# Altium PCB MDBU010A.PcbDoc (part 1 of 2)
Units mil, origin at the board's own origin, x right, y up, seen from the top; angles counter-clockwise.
Board outline 3300 x 2500 mil, 2 copper layers (Top Layer, Bottom Layer), stack 64.8 mil thick; 105 components, 70 nets, 307 pads, 460 vias.
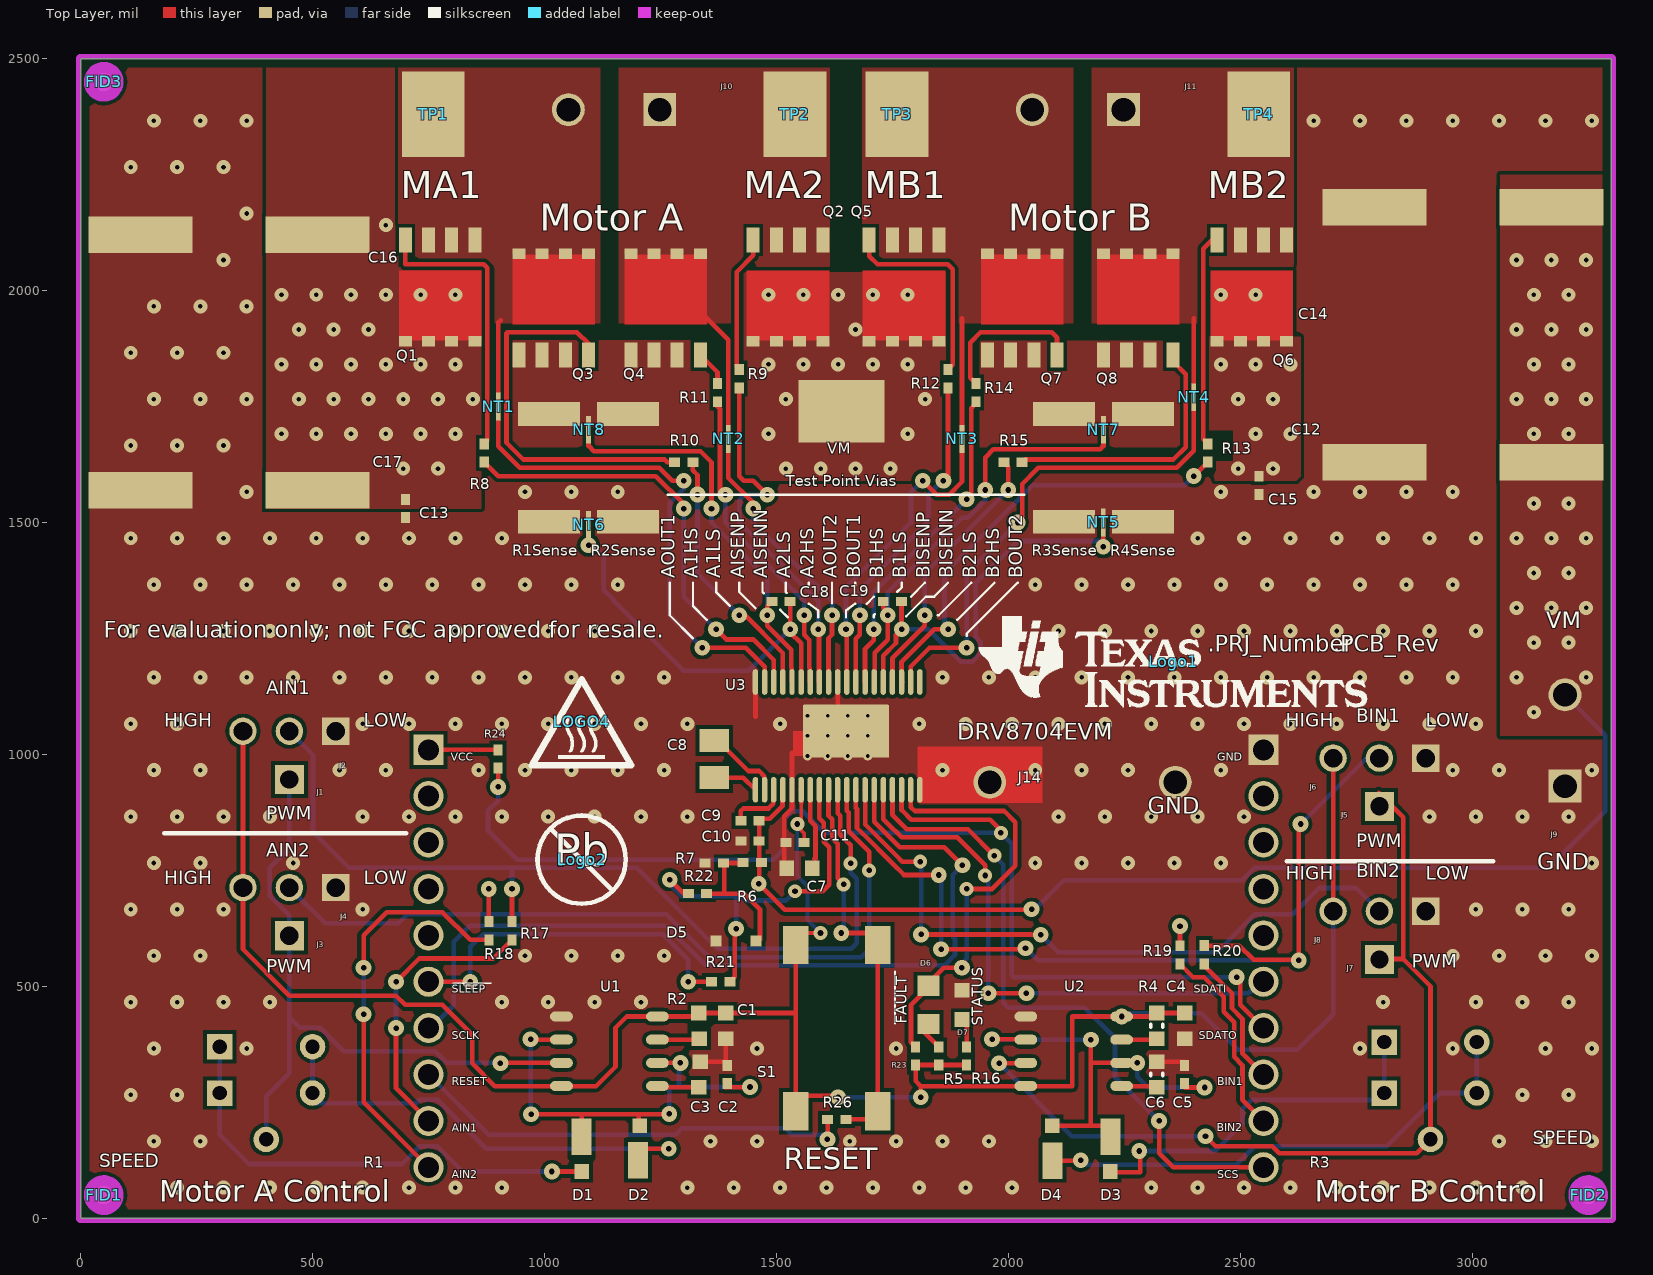
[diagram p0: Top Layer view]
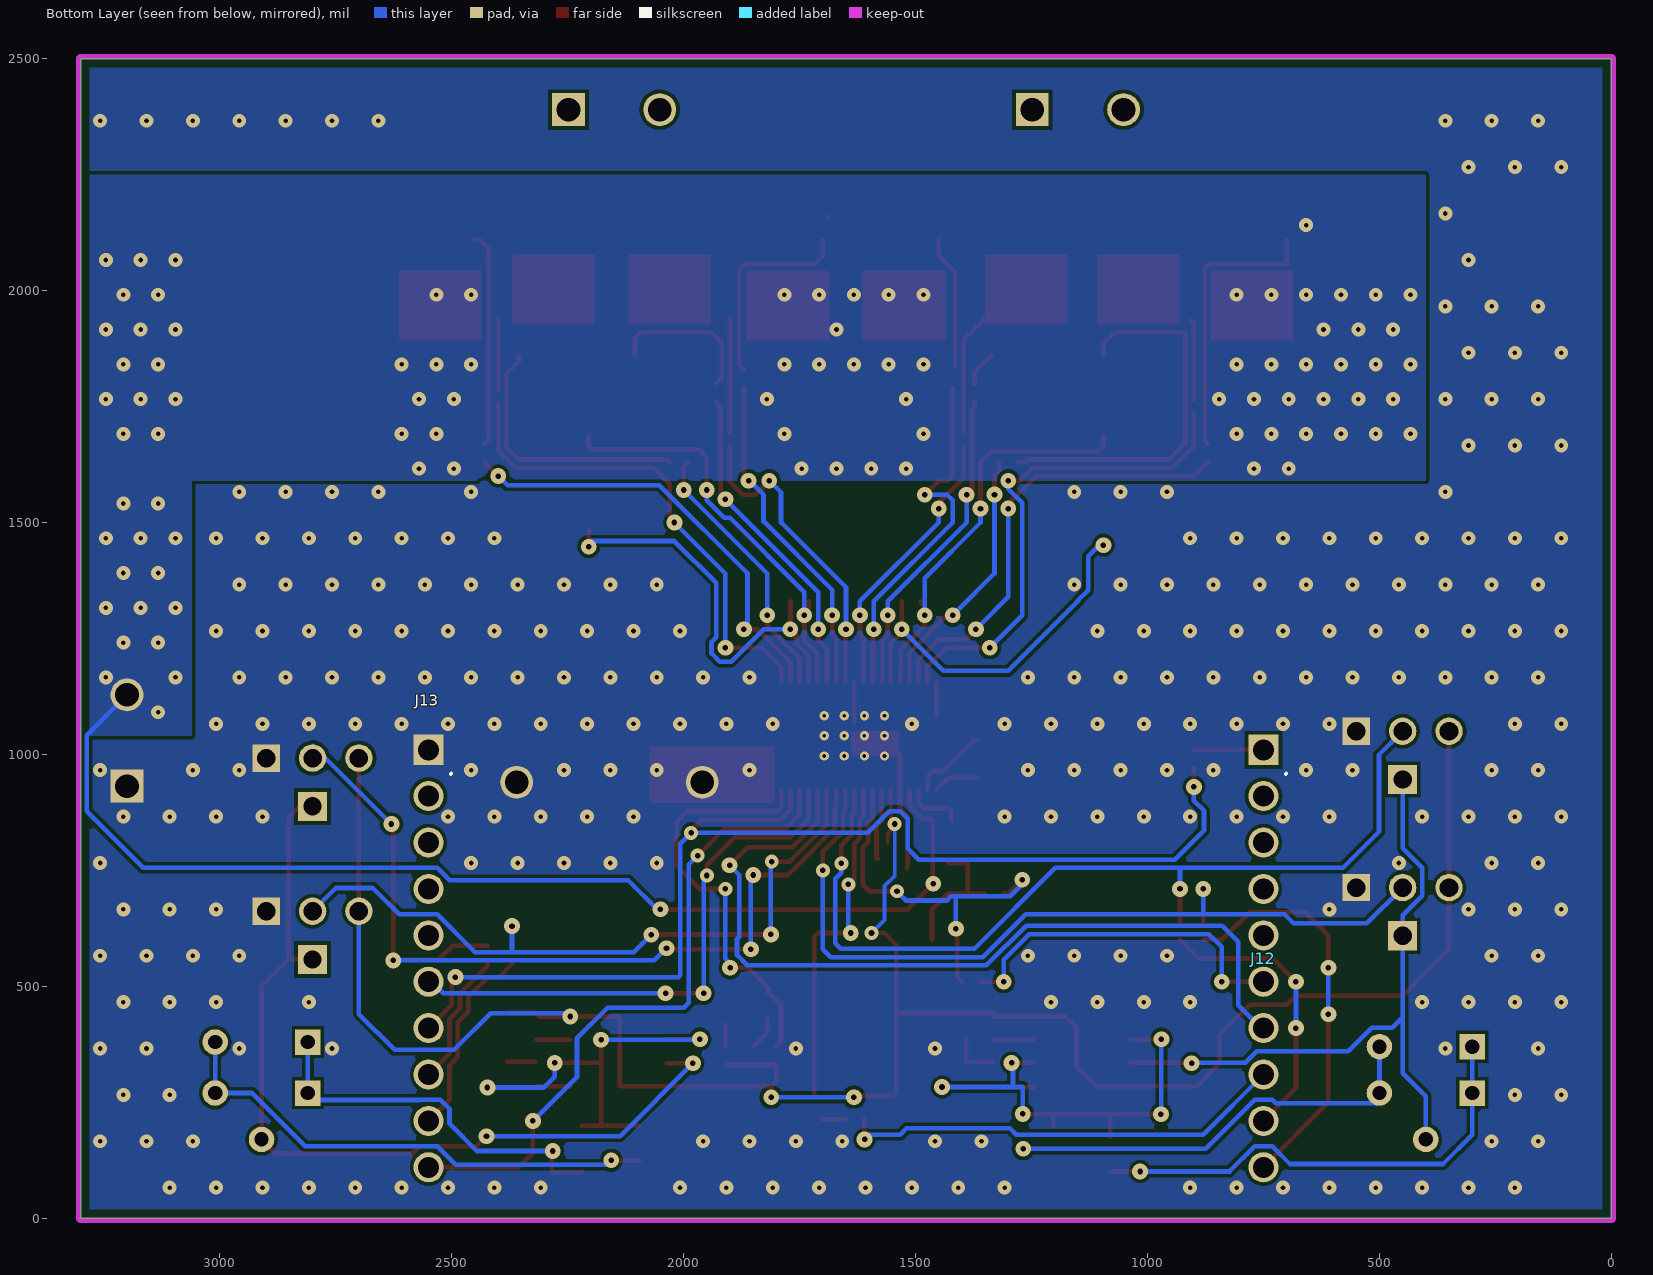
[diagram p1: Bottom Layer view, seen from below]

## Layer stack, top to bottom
Top Solder: solder mask 0.4, Solder Resist, Dk 3.5
Top Layer: signal copper 2.8
Dielectric1: core 59.2, FR-4, Dk 4.8
Bottom Layer: signal copper 2.8
Bottom Solder: solder mask 0.4, Solder Resist, Dk 3.5

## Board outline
0,0 3300,0 3300,2500 0,2500

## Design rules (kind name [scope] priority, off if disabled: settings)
AcuteAngle [All] p1: minimum=4.50000000000000E+0001 checktracksonly=FALSE
AssemblyTestPointUsage [All] p1: valid=2
Clearance [All] p1: gap=7.87
Clearance Clearance_2 [All] p2: gap=10
Clearance Clearance_1 [All] p3: gap=10
Clearance Clearance_Keepouts [((IsTrack Or IsArc) And Not InPoly) And IsFree and IsKeepOut vs ((IsTrack Or IsArc) And Not InPoly) And IsFree and IsKeepOut] p4: gap=0
Clearance Clearance_BoardEdge_MountingHoles [OnCopper and InComponentClass('Mounting Holes') vs IsKeepOut] p5: gap=40
Clearance Clearance_BoardEdge_Poly [OnCopper and InPoly vs IsKeepOut] p6: gap=25
Clearance Clearance_BoardEdge [OnCopper and Not InComponentClass('Logo') and not InComponentClass('FiducialMark') and not InRegion(1000,500,4000,800) and Not IsKeepout vs IsKeepOut] p7: gap=75
Clearance Clearance_Poly [InPolygon] p8: gap=25
ComponentClearance ComponentClearance_MountingHoles_FiducialMarks [InComponentClass('Mounting Holes') vs InComponentClass('FiducialMark')] p1: gap=50 collisioncheckmode=3 verticalgap=10 showdistances=FALSE
ComponentClearance ComponentClearance_Shunt [InComponentClass('Header') vs InComponentClass('Shunt')] p2: gap=0 collisioncheckmode=3 verticalgap=0 showdistances=FALSE
ComponentClearance ComponentClearance_Logo [InComponentClass('Logo')] p3: gap=50 collisioncheckmode=3 verticalgap=10 showdistances=FALSE
ComponentClearance ComponentClearance_ScrewToNut [(HasFootprint('NY PMS 440 0025 PH')) vs (HasFootprint('Keystone_1902C'))] p4: gap=5 collisioncheckmode=3 verticalgap=10 showdistances=FALSE
ComponentClearance ComponentClearance_MountingHoles [InComponentClass('Mounting Holes')] p5: gap=250 collisioncheckmode=3 verticalgap=100000 showdistances=FALSE
ComponentClearance ComponentClearance_SmallPassives [HasFootprint('0201*') or HasFootprint('0402*') or HasFootprint('0508') or HasFootprint('0603*') or HasFootprint('0612') or HasFootprint('0805*') or HasFootprint('0815*') or HasFootprint('0830*') or HasFootprint('1206*') or HasFootprint('1210*') or HasFootprint('1808*') or HasFootprint('1812*') or HasFootprint('1825*') or HasFootprint('2010*') or HasFootprint('2220*') or HasFootprint('2225*') or HasFootprint('2512*') or HasFootprint('2728*') or HasFootprint('3518*') vs HasFootprint('0201*') or HasFootprint('0402*') or HasFootprint('0508') or HasFootprint('0603*') or HasFootprint('0612') or HasFootprint('0805*') or HasFootprint('0815*') or HasFootprint('0830*') or HasFootprint('1206*') or HasFootprint('1210*') or HasFootprint('1808*') or HasFootprint('1812*') or HasFootprint('1825*') or HasFootprint('2010*') or HasFootprint('2220*') or HasFootprint('2225*') or HasFootprint('2512*') or HasFootprint('2728*') or HasFootprint('3518*')] p6: gap=20 collisioncheckmode=3 verticalgap=10 showdistances=FALSE
ComponentClearance ComponentClearance_THtoSMT [IsThruComponent vs IsSMTComponent] p7: gap=100 collisioncheckmode=3 verticalgap=30 showdistances=FALSE
ComponentClearance ComponentClearance_THtoTH [IsThruComponent vs IsThruComponent] p8: gap=1 collisioncheckmode=3 verticalgap=0 showdistances=FALSE
ComponentClearance [All] p9: gap=10 collisioncheckmode=3 verticalgap=10 showdistances=FALSE
DiffPairsRouting [All] p1: maxlimit=100 minlimit=10 mostfreqgap=10 toplayer_minwidth=15 toplayer_maxwidth=15 toplayer_prefwidth=15 bottomlayer_minwidth=15 bottomlayer_maxwidth=15 bottomlayer_prefwidth=15 maxuncoupledlength=1000
FabricationTestPointUsage TestPointUsage [All] p1: valid=2 allowmultiple=FALSE
FabricationTestpoint Testpoint [All] p1: side=3 testpointundercomponent=TRUE minsize=40 maxsize=100 preferedsize=60 minholesize=0 maxholesize=40 preferedholesize=32 testpointgrid=1 allowsidetop=TRUE allowsidebottom=TRUE usegrid=TRUE gridtolerance=0.01
FanoutControl Fanout_LCC [IsLCC] p1: bgadir=Out bgaviamode=Centered fanoutstyle=Auto fanoutdirection=Alternating viagrid=1 // Fanout_LCC (Default Rule)
FanoutControl Fanout_BGA [IsBGA] p2: bgadir=Out bgaviamode=Centered fanoutstyle=Auto fanoutdirection=Alternating viagrid=1 // Fanout_BGA (Default Rule)
FanoutControl Fanout_Default [All] p4: bgadir=Out bgaviamode=Centered fanoutstyle=Auto fanoutdirection=Alternating viagrid=1 // Fanout_Default (Default Rule)
FanoutControl Fanout_Small [(CompPinCount < 5)] p5: bgadir=Out bgaviamode=Centered fanoutstyle=Auto fanoutdirection=OutThenIn viagrid=1 // Fanout_Small (Default Rule)
HoleSize [All] p1: absolutevalues=TRUE maxlimit=251 minlimit=7.87 maxpercent=80.000 minpercent=20.000
MinimumAnnularRing MinimumAnnularRing_ThermalPadVias [IsVia and InAnyComponent] p1: minimumring=5.91
MinimumAnnularRing [All] p2: minimumring=9
MinimumSolderMaskSliver MinimumSolderMaskSliver_Logo [InComponentClass('Logo') vs InComponentClass('Logo')] p1: minsoldermaskwidth=0.7
MinimumSolderMaskSliver [All] p2: minsoldermaskwidth=3.94
PlaneConnect [All] p1: planeconnectstyle=Relief reliefexpansion=10 reliefentries=4 reliefconductorwidth=10 reliefairgap=10
PolygonConnect [All] p1: connectstyle=Direct reliefconductorwidth=10 reliefentries=4 polygonreliefangle="90 Angle" airgapwidth=10
RoutingVias ThermalPadVias [IsVia and InAnyComponent] p1: holewidth=7.87 width=19.68 viastyle="Through Hole" minholewidth=7.87 minwidth=19.68 maxholewidth=12.99 maxwidth=23.62
RoutingVias [All] p2: holewidth=16 width=34 viastyle="Through Hole" minholewidth=7.87 minwidth=26 maxholewidth=21 maxwidth=65
SilkToSilkClearance SilkToSilkClearance_Pb-FreeLogo [(HasFootprint('Pb-Free_Overlay_Medium') OR HasFootprint('Pb-Free_Overlay_Small')) vs (HasFootprint('Pb-Free_Overlay_Medium') OR HasFootprint('Pb-Free_Overlay_Small'))] p1: silktosilkclearance=0
SilkToSilkClearance [All] p2: silktosilkclearance=4
SilkToSolderMaskClearance SilkToComonentPadClearance [IsPad and InAnycomponent] p1: minsilkscreentomaskgap=5 clearancetoexposedcopper=TRUE
SilkToSolderMaskClearance "Silk to Solder Mask Opening" [All] p2: minsilkscreentomaskgap=4 clearancetoexposedcopper=FALSE
SolderMaskExpansion [All] p1: expansion=1.97
UnpouredPolygon [All] p1: allowunpoured=FALSE
Width [All] p1: maxlimit=100 minlimit=6 preferedwidth=10 checkconnectedcopper=TRUE
15 further rules are at their usual default settings.

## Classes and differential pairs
component class FiducialMark: FID1 FID2 FID3
component class Logo: Logo1
component class MDBU010A_Hardware: !PCB FID1 FID2 FID3 J14 Logo1 Logo2 Logo3 LOGO4 ZZ1 ZZ2 ZZ3 ZZ4
component class AssemblyNote: ZZ1 ZZ2 ZZ3 ZZ4
component class MDBU010A: 20 C1 C2 C3 C4 C5 C6 C7 C8 C9 C10 C11 C12 C13 C14 C15 C16 C17 C18 C19 D1 D2 D3 D4 D5 D6 D7 J1 J2 J3 J4 J5 J6 J7 J8 J9 J10 J11 J12 J13 NT1 NT2 NT3 NT4 NT5 NT6 NT7 NT8 Q1 Q2 Q3 Q4 Q5 Q6 Q7 Q8 R1 R1Sense R2 R2Sense R3 R3Sense R4 R4Sense R5 R6 R7 R8 R9 R10 R11 R12 R13 R14 R15 R16 R17 R18 R19 R20 R21 R22 R23 R24 R26 S1 TP1 TP2 TP3 TP4 U1 U2 U3 VM
component class Header: J2 J4 J6 J8

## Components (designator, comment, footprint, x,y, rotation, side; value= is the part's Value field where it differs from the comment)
C1 "C0603C104M4RACTU" 0603L#1 1391,415 r90 top
C2 "GCM155R71E103KA37D" 0402L 1394,310 r270 top
C3 "C0603X103K5RACTU" 0603L#2 1336,310 r270 top
C4 "C0603C104M4RACTU" 0603L#1 2380,415 r90 top
C5 "GCM155R71E103KA37D" 0402L 2380,310 r270 top
C6 "C0603X103K5RACTU" 0603L#1 2320,310 r270 top
C7 "EMK107B7105KA-T" 0603L#1 1550,755 r180 top
C8 "GRM21BR71H104KA01L" 0805_HV 1366,990 r270 top
C9 "EMK105BJ105KVHF" 0402L 1443,857 r0 top
C10 "C0402C103J5RACTU" 0402L 1443,813 r0 top
C11 "GRM155R61A104KA01D" 0402L 1540,810 r180 top
C12 "EEE-TK1J221AQ" SM_RADIAL_H13 2980,1630 r180 top
C13 "C1005X7R1H104K050BB" 0402L 700,1530 r270 top
C14 "EEE-TK1J221AQ" SM_RADIAL_H13 2980,2180 r180 top
C15 "C1005X7R1H104K050BB" 0402L 2540,1580 r270 top
C16 "EEE-TK1J221AQ" SM_RADIAL_H13 320,2120 r180 top
C17 "EEE-TK1J221AQ" SM_RADIAL_H13 320,1570 r180 top
C18 "C1005C0G1E102J" 0402L 1510,1330 r0 top
C19 "C1005C0G1E102J" 0402L 1750,1330 r0 top
D1 "MSS1P4-M3/89A" MicroSMP#1 1080,150 r270 top
D2 "MSS1P4-M3/89A" MicroSMP#2 1205,150 r90 top
D3 "MSS1P4-M3/89A" MicroSMP#1 2220,150 r270 top
D4 "MSS1P4-M3/89A" MicroSMP#1 2095,150 r90 top
D5 "CMDZ5L1 TR" sod-323 1413.16,597.59 r180 top
D6 "150080SS75000" WL-SMCW_RED_0805 1828,460 r270 top
D7 "150060VS75000" WL-SMCW_GREEN 1900,460 r270 top
FID1 "Fiducial" Fiducial10-20 50,50 r0 top
FID2 "Fiducial" Fiducial10-20 3250,50 r0 top
FID3 "Fiducial" Fiducial10-20 50,2450 r0 top
J1 "PEC01SAAN" Sullins_PEC01SAAN#1 450,946 r0 top
J2 "PEC03SAAN" CONN_PEC03SAAN 450,1050 r180 top
J3 "PEC01SAAN" Sullins_PEC01SAAN#2 450,609 r180 top
J4 "PEC03SAAN" CONN_PEC03SAAN 450,713 r180 top
J5 "PEC01SAAN" Sullins_PEC01SAAN#2 2800,888 r90 top
J6 "PEC03SAAN" CONN_PEC03SAAN 2800,991.98 r180 top
J7 "PEC01SAAN" Sullins_PEC01SAAN#2 2800,558 r90 top
J8 "PEC03SAAN" CONN_PEC03SAAN 2800,661.98 r180 top
J9 "691 101 710 002" Wurth_691101710002 3200,1030 r90 top
J10 "691 101 710 002" Wurth_691101710002 1150,2390 r180 top
J11 "691 101 710 002" Wurth_691101710002 2150,2390 r180 top
J12 "SSW-110-23-F-S" CONN_SSW-110-23-F-S 750,560 r90 bottom
J13 "SSW-110-23-F-S" CONN_SSW-110-23-F-S 2550,560 r90 bottom
J14 "D3082-05" Harwin_D3082-05 2160,940 r180 top
Logo1 "Texas Instruments" TI_Stacked_Overlay_Small 2355,1200 r0 top
Logo2 "Pb-Free Symbol" Pb-Free_Overlay_Medium 1080,773.23 r0 top
Logo3 "FCC disclaimer" FCC_disclaimer 6220,6840 r90 top
LOGO4 "CAUTION HOT SURFACE" IEC_HotSurface_Small 1080,1070 r0 top
NT1 "Net-Tie" Net-Tie_10milWide_30milLong#1 900,1750 r90 top net-tie
NT2 "Net-Tie" Net-Tie_10milWide_30milLong#2 1400,1680 r270 top net-tie
NT3 "Net-Tie" Net-Tie_10milWide_30milLong#1 1900,1680 r90 top net-tie
NT4 "Net-Tie" Net-Tie_10milWide_30milLong#1 2400,1770 r270 top net-tie
NT5 "Net-Tie" Net-Tie_10milWide_30milLong#3 2196.77,1500 r90 top net-tie
NT6 "Net-Tie" Net-Tie_10milWide_30milLong#4 1100,1490 r90 top net-tie
NT7 "Net-Tie" Net-Tie_10milWide_30milLong#5 2210,1700 r90 top net-tie
NT8 "Net-Tie" Net-Tie_10milWide_30milLong#6 1090,1700 r90 top net-tie
Q1 "CSD18540Q5B" TRANS_NexFET_Q5B 775,2000 r270 top
Q2 "CSD18540Q5B" TRANS_NexFET_Q5B 1525,2000 r270 top
Q3 "CSD18540Q5B" TRANS_NexFET_Q5B 1020,1970 r90 top
Q4 "CSD18540Q5B" TRANS_NexFET_Q5B 1261,1970 r90 top
Q5 "CSD18540Q5B" TRANS_NexFET_Q5B 1775,2000 r270 top
Q6 "CSD18540Q5B" TRANS_NexFET_Q5B 2525,2000 r270 top
Q7 "CSD18540Q5B" TRANS_NexFET_Q5B 2030,1970 r90 top
Q8 "CSD18540Q5B" TRANS_NexFET_Q5B 2280,1970 r90 top
R1 "3386P-1-502LF" BOURNS_3386P 400,280 r0 top
R1Sense "CSRN2512FK15L0" 2512 1010,1617.87 r90 top
R2 "ERJ-3EKF1002V" 0603L#3 1333.32,415 r90 top
R2Sense "CSRN2512FK15L0" 2512 1180,1617.87 r90 top
R3 "3386P-1-502LF" BOURNS_3386P 2910,280 r0 top
R3Sense "CSRN2512FK15L0" 2512 2120,1617.87 r90 top
R4 "ERJ-3EKF1002V" 0603L#1 2320,415 r90 top
R4Sense "CSRN2512FK15L0" 2512 2290,1617.87 r90 top
R5 "CRCW0402200RFKED" 0402L 1850,350 r90 top
R6 "CRCW0402100KJNED" 0402L 1448,767 r0 top
R7 "CRCW0402100KJNED" 0402L 1366,766 r0 top
R8 "CRCW04020000Z0ED" 0402L 870,1650 r90 top
R9 "CRCW04020000Z0ED" 0402L 1420,1810 r270 top
R10 "CRCW04020000Z0ED" 0402L 1300,1630 r180 top
R11 "CRCW04020000Z0ED" 0402L 1373,1780 r270 top
R12 "CRCW04020000Z0ED" 0402L 1870,1810 r90 top
R13 "CRCW04020000Z0ED" 0402L 2430,1650 r270 top
R14 "CRCW04020000Z0ED" 0402L 1930,1780 r90 top
R15 "CRCW04020000Z0ED" 0402L 2010,1630 r180 top
R16 "CRCW0402200RFKED" 0402L 1910,350 r270 top
R17 "CRCW04020000Z0ED" 0402L 930,620 r90 top
R18 "CRCW04020000Z0ED" 0402L 880,620 r90 top
R19 "CRCW04020000Z0ED" 0402L 2370,567.81 r90 top
R20 "CRCW04020000Z0ED" 0402L 2422.28,568.17 r90 top
R21 "CRCW04020000Z0ED" 0402L 1380,510 r0 top
R22 "CRCW04020000Z0ED" 0402L 1330,700 r0 top
R23 "CRCW040210K0JNED" 0402L 1800,350 r270 top
R24 "CRCW04023K30JNED" 0402L 900,990 r90 top
R26 "CRCW04020000Z0ED" 0402L 1629.99,213.14 r0 top
S1 "4-1437565-1" SW_FSM4JSMA 1630,410 r180 top
TP1 "5016" Testpoint_Keystone_Compact 760,2380 r270 top
TP2 "5016" Testpoint_Keystone_Compact 1540,2380 r270 top
TP3 "5016" Testpoint_Keystone_Compact 1760,2380 r90 top
TP4 "5016" Testpoint_Keystone_Compact 2540,2380 r90 top
U1 "TLC555CD" D0008A_L 1140,360 r0 top
U2 "TLC555CD" D0008A_L 2141,360 r0 top
U3 "DRV8704DCPR" DCP0038A_N 1632,1040 r90 top
VM "5016" Testpoint_Keystone_Compact 1640,1740 r0 top (schematic designator TP5)
ZZ1 "Shorting plug J14 shall be raised to minimum height of 250mils above PCB" AssemblyNote 10,3330 r0 top
ZZ2 "These assemblies are ESD sensitive, ESD precautions shall be observed." AssemblyNote 10,3160 r0 top
ZZ3 "These assemblies must be clean and free from flux and all contaminants. Use of no clean flux is not acceptable." AssemblyNote 10,2980 r0 top
ZZ4 "These assemblies must comply with workmanship standards IPC-A-610 Class 2, unless otherwise specified." AssemblyNote 10,2810 r0 top

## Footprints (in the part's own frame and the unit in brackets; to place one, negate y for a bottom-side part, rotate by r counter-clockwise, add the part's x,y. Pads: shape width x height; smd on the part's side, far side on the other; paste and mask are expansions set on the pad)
0402L [mm] "0402 from SM-752 data"
  rect 0.6x0.5 smd: 1(-0.5,0) 2(0.5,0)
  body extent -0.55,-0.3 0.55,0.3, height 0.6
0603L#1 [mm] "0603 from SM-752 data"
  rect 0.8x0.85 smd: 1(-0.7,0) 2(0.7,0)
  body extent -0.87,-0.47 0.87,0.47, height 0.85
0603L#2 [mm] "0603 from SM-752 data"
  rect 0.8x0.85 smd: 1(-0.7,0) 2(0.7,-0.076)
  body extent -0.87,-0.47 0.87,0.47, height 0.85
0603L#3 [mm] "0603 from SM-752 data"
  rect 0.8x0.85 smd: 1(-0.7,0) 2(0.7,0.008)
  body extent -0.87,-0.47 0.87,0.47, height 0.85
0805_HV [mil] "0805 with 30mil clearance between pads"
  rect 50x63 smd: 1(-40,0) 2(40,0)
  body extent -43,-29 43,29, height 57
2512 [mm] "Chip Resistor, Body 6.3x3.2mm, IPC Medium Density"
  rect 1.3x3.4 smd: 1(-2.95,0) 2(2.95,0)
  body extent -3.22,-1.67 3.22,1.67, height 0.71
AssemblyNote [mil] "Assembly Note"
BOURNS_3386P [mil] "BOURND"
  rect 55x55 hole 31: 1(-100,-10)
  round 55 hole 31: 2(0,-110) 3(100,-10)
  body extent -193,-192 193,193, height 201
CONN_PEC03SAAN [mm] "SULLINS"
  rect 1.5x1.5 hole 1.016: 1(-2.54,0)
  round 1.5 hole 1.016: 2(0,0) 3(2.54,0)
  body extent -3.84,-1.3 3.84,1.3, height 8.38
CONN_SSW-110-23-F-S [mm] "SAMTEC"
  rect 1.65x1.65 hole 1.15: 1(11.43,0)
  round 1.65 hole 1.15: 2(8.89,0) 3(6.35,0) 4(3.81,0) 5(1.27,0) 6(-1.27,0) 7(-3.81,0) 8(-6.35,0) 9(-8.89,0) 10(-11.43,0)
  silkscreen extent 10.11,-1.24 10.13,-1.22, body extent -13,-1.27 13,1.27, height 8.59
D0008A_L [mm] "SOIC, 8-Leads, Body 4.9x3.9mm, Pitch 1.27mm, IPC High Density"
  oval 1.25x0.55 smd: 1(-2.625,1.905) 2(-2.625,0.635) 3(-2.625,-0.635) 4(-2.625,-1.905) 5(2.625,-1.905) 6(2.625,-0.635) 7(2.625,0.635) 8(2.625,1.905)
  body extent -3,-2.45 3,2.45, height 1.63
DCP0038A_N [mm] "SOP, 38-Leads, Body 9.8x4.5mm, Pitch 0.5mm, Thermal Pad 4.7x2.9mm, IPC Medium Density"
  oval 1.4x0.3 smd: 1(-2.95,4.5) 2(-2.95,4) 3(-2.95,3.5) 4(-2.95,3) 5(-2.95,2.5) 6(-2.95,2) 7(-2.95,1.5) 8(-2.95,1) 9(-2.95,0.5) 10(-2.95,0) 11(-2.95,-0.5) 12(-2.95,-1) 13(-2.95,-1.5) 14(-2.95,-2) 15(-2.95,-2.5) 16(-2.95,-3) 17(-2.95,-3.5) 18(-2.95,-4) 19(-2.95,-4.5) 20(2.95,-4.5) 21(2.95,-4) 22(2.95,-3.5) 23(2.95,-3) 24(2.95,-2.5) 25(2.95,-2) 26(2.95,-1.5) 27(2.95,-1) 28(2.95,-0.5) 29(2.95,0) 30(2.95,0.5) 31(2.95,1) 32(2.95,1.5) 33(2.95,2) 34(2.95,2.5) 35(2.95,3) 36(2.95,3.5) 37(2.95,4) 38(2.95,4.5)
  rrect3% 2.9x4.7 smd: 39(0.254,-0.457)
  body extent -3.21,-4.85 3.21,4.85, height 1.2
FCC_disclaimer [mil]
Fiducial10-20 [mm]
  round 1 smd mask+0.5: 1(0,0)
  Top Layer keep-out circle w1.178: c0,0 r0.5
Harwin_D3082-05 [mm] "Shorting Plug, 10.16mm spacing, TH"
  round 1.8 hole 1.3: 1(-5.08,0) 2(5.08,0)
  body extent -5.6,-0.52 5.61,0.52, height 6.63
IEC_HotSurface_Small [mil]
  silkscreen extent -107,-93 107,92
MicroSMP#1 [mm] "SMD, 2-Leads, Body 2.2x1.3mm"
  rect 2x1.1 smd: 1(-0.65,0)
  rect 0.8x0.8 smd: 2(1.25,0)
  body extent -1.15,-0.7 1.15,0.7, height 0.75
MicroSMP#2 [mm] "SMD, 2-Leads, Body 2.2x1.3mm"
  rect 2x1.1 smd: 1(-0.635,0.084)
  rect 0.8x0.8 smd: 2(1.25,0)
  body extent -1.15,-0.7 1.15,0.7, height 0.75
Net-Tie_10milWide_30milLong#1 [mil] "10mil net tie, no solder mask opening, no solder paste"
  rect 30x10 smd paste-5 mask-5: 1(-15,0) 2(15,0)
Net-Tie_10milWide_30milLong#2 [mil] "10mil net tie, no solder mask opening, no solder paste"
  rect 30x10 smd paste-5 mask-5: 1(-15,-3.61) 2(15,-3.61)
Net-Tie_10milWide_30milLong#3 [mil] "10mil net tie, no solder mask opening, no solder paste"
  rect 30x10 smd paste-5 mask-5: 1(-15,-7.89) 2(15,-7.89)
Net-Tie_10milWide_30milLong#4 [mil] "10mil net tie, no solder mask opening, no solder paste"
  rect 30x10 smd paste-5 mask-5: 1(-10,5) 2(20,5)
Net-Tie_10milWide_30milLong#5 [mil] "10mil net tie, no solder mask opening, no solder paste"
  rect 30x10 smd paste-5 mask-5: 1(-15,5) 2(15,5)
Net-Tie_10milWide_30milLong#6 [mil] "10mil net tie, no solder mask opening, no solder paste"
  rect 30x10 smd paste-5 mask-5: 1(-15,-5) 2(15,-5)
Pb-Free_Overlay_Medium [mil]
  silkscreen extent -95,-95 95,95
SM_RADIAL_H13 [mm] "12.5 x 13.5mm:  Panasonic H13"
  rect 5.7x2 smd: 1(-4.85,0) 2(4.85,0)
  body extent -6.85,-6.85 6.85,6.85, height 14
sod-323 [mm] "NXP recommended land pattern"
  rect 0.6x0.6 smd paste-0.05: 1(-1.1,0) 2(1.1,0)
  body extent -1.3,-0.67 1.3,0.68, height 1.1
Sullins_PEC01SAAN#1 [mm] "SULLINS"
  rect 1.6x1.6 hole 1: 1(0,-0.005)
  body extent -1.3,-1.3 1.3,1.3, height 8.38
Sullins_PEC01SAAN#2 [mm] "SULLINS"
  rect 1.6x1.6 hole 1: 1(0,0)
  body extent -1.3,-1.3 1.3,1.3, height 8.38
SW_FSM4JSMA [mm] "Alcoswitch"
  rect 1.4x2.1 smd: 1(2.25,4.55) 2(2.25,-4.55) 3(-2.25,4.55) 4(-2.25,-4.55)
  body extent -3,-5 3,5, height 5.1
Testpoint_Keystone_Compact [mil] "Compact SMT test point"
  rect 185x135 smd: 1(0,0)
  body extent -75,-56 75,56, height 91
TI_Stacked_Overlay_Small [mil]
  silkscreen extent -418,-98 418,98
TRANS_NexFET_Q5B [mm] "TI recommended land pattern (nominal) November 2012"
  rect 1.372x0.71 smd paste-0.4: 1(-2.776,1.905) 2(-2.776,0.635) 3(-2.776,-0.635) 4(-2.776,-1.905)
  rect 0.59x0.71 smd paste-0.3: 5(2.776,-1.905) 6(2.776,-0.635) 7(2.776,0.635) 8(2.776,1.905)
  Top Layer region: -1.106,-2.26 2.744,-2.26 2.744,2.26 -1.106,2.26
  body extent -3.23,-2.55 2.87,2.55, height 1.06
WL-SMCW_GREEN [mm] "WURTH"
  rect 0.8x0.8 smd: 1(-0.8,0) 2(0.8,0)
  body extent -0.85,-0.45 0.85,0.45, height 0.8
WL-SMCW_RED_0805 [mm] "SMD, 2-Leads, Body 1.6x0.8mm"
  rect 1.1x1.2 smd: 1(-1.05,0) 2(1.05,0)
  body extent -1,-0.62 1,0.63, height 0.7
Wurth_691101710002 [mm] "Terminal Block, 5 mm, 2x1, TH"
  rect 1.8x1.8 hole 1.3: 1(-2.5,0)
  round 1.8 hole 1.3: 2(2.5,0)
  body extent -5.6,-4 5.6,5, height 12.5

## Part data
C1 C4: "CAP, CERM, 0.1 µF, 16 V, +/- 20%, X7R, 0603"
C2 C5: "CAP, CERM, 0.01 µF, 25 V, +/- 10%, X7R, 0402"
C3 C6: "CAP, CERM, 0.01 µF, 50 V, +/- 10%, X7R, 0603"
C7: "CAP, CERM, 1 µF, 16 V, +/- 10%, X7R, 0603"
C8: "CAP, CERM, 0.1 µF, 50 V, +/- 10%, X7R, 0805"
C9: "CAP, CERM, 1 µF, 16 V, +/- 10%, X5R, 0402"
C10: "CAP, CERM, 0.01 µF, 50 V, +/- 5%, X7R, 0402"
C11: "CAP, CERM, 0.1 µF, 10 V, +/- 10%, X5R, 0402"
C12 C14 C16 C17: "CAP, AL, 220 µF, 63 V, +/- 20%, 0.26 ohm, AEC-Q200 Grade 1, SMD"
C13 C15: "CAP, CERM, 0.1 µF, 50 V, +/- 10%, X7R, 0402"
C18 C19: "CAP, CERM, 1000 pF, 25 V, +/- 5%, C0G/NP0, 0402"
D1 D2 D3 D4: "Diode, Schottky, 40 V, 1 A, MicroSMP"
D5: "Diode, Zener, 5.1 V, 250 mW, SOD-323"
D6: "LED, Red, SMD"
D7: "LED, Green, SMD"
FID1 FID2 FID3: "Fiducial mark.  There is nothing to buy or mount."
J1 J3 J5 J7: "Header, 1x1, Tin, TH"
J2 J4 J6 J8: "Header, 100mil, 3x1, Tin, TH"
J9 J10 J11: "Terminal Block, 5 mm, 2x1, Tin, TH"
J12 J13: "Connector, Receptacle, 100mil, 10x1, Gold plated, TH"
J14: "1mm Uninsulated Shorting Plug, 10.16mm spacing, TH"
Logo1: library part TI_Logo, "Texas Instrument Corporate Signature"
Logo2: library part Pb-Free
Logo3: library part FCC_disclaimer, "FCC_disclaimer"
LOGO4: library part IEC_HotSurface, "IEC 61010-1 Hot Surface Warning"
NT1 NT2 NT3 NT4 NT5 NT6 NT7 NT8: "Single point connection between nets."
Q1 Q2 Q3 Q4 Q5 Q6 Q7 Q8: "MOSFET, N-CH, 60 V, 28 A, SON 5x6mm"
R1 R3: "TRIMMER, 5k ohm, 0.5W, TH"
R1Sense R2Sense R3Sense R4Sense: "RES, 0.015, 1%, 2 W, 2512"
R2 R4: "RES, 10.0 k, 1%, 0.1 W, 0603"
R5 R16: "RES, 200, 1%, 0.063 W, 0402"
R6 R7: "RES, 100 k, 5%, 0.063 W, 0402"
R8 R9 R10 R11 R12 R13 R14 R15 R17 R18 R19 R20 R21 R22 R26: "RES, 0, 5%, 0.063 W, 0402"
R23: "RES, 10 k, 5%, 0.063 W, 0402"
R24: "RES, 3.3 k, 5%, 0.063 W, 0402"
S1: "Switch, Tactile, SPST-NO, 0.05A, 12V, SMT"
TP1 TP2 TP3 TP4 VM: "Test Point, Compact, SMT"
U1 U2: "LinCMOS Timer, D0008A"
U3: "52-V Dual H-Bridge PWM Gate Driver, DCP0038A"
ZZ1 ZZ2 ZZ3 ZZ4: library part AssemblyNote

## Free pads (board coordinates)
  rect 55x55 hole 31: 0(300,370) 0(2810,380)
  round 55 hole 31: 1(500,370) 1(3010,380)

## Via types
v1: diameter 30, hole 10, Top Layer to Bottom Layer, tented both sides, 357 vias
v2: diameter 34, hole 12, Top Layer to Bottom Layer, 60 vias
v3: diameter 34, hole 12, Top Layer to Bottom Layer, tented top, 20 vias
v4: diameter 20, hole 8, Top Layer to Bottom Layer, 12 vias
v5: diameter 30, hole 12, Top Layer to Bottom Layer, 11 vias

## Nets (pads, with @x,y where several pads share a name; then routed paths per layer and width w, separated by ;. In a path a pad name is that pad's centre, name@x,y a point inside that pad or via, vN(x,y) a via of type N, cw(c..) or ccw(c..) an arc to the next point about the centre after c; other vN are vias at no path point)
\SLEEP: R21.2 R22.1 U3.8 | length 835.4
  Top Layer w10: v2(1270,730) 1300,700 R22.1@1310.32,700 ; R21.2@1399.69,510 1410,520.31 1410,621.01 v2(1413.15,624.16) ; v5(1540,705) 1600,705 1614.06,719.06 1614.06,800.02 1602.24,811.83 1602.24,852.58 1592.63,862.19 U3.8@1592.63,923.86
  Bottom Layer w10: v2(1270,730) 1270,720 1296.13,693.87 1423.98,693.87 1432.85,685 1520,685 v5(1540,705) ; v2(1413.15,624.16) 1413.15,690.72
A1HS: R8.1 U3.36 | length 951.4
  Top Layer w10: R8.1@870,1630.32 900.32,1600 1240,1600 1300,1540 v3(1300,1530) ; v2(1370,1270) 1392.13,1247.87 1449.88,1247.87 1494.2,1203.55 U3.36@1494.2,1156.14
  Bottom Layer w10: v3(1300,1530) 1300,1340 v2@1360,1280
A1LS: R10.1 U3.35 | length 535
  Top Layer w10: R10.1@1319.68,1630 1319.68,1612.56 1329.87,1602.37 v3(1329.87,1560.13) ; v2@1432.47,1300 1513.89,1218.58 U3.35@1513.89,1156.14
  Bottom Layer w10: v3(1329.87,1560.13) 1330,1560 1330,1390 v2@1410,1310
  other v2: 1420,1300
A2HS: R9.2 U3.31 | length 805.8
  Top Layer w10: R9.2@1420,1790.31 1420,1600 1430,1590 1450,1590 v3(1480,1560) ; v2@1581.51,1261.51 v2(1590,1270) 1591.72,1268.28 U3.31@1591.72,1157.05
  Bottom Layer w10: v3(1480,1560) 1432.25,1560 1420,1547.75 1420,1500 1590,1330 v2(1590,1270)
A2LS: R11.2 U3.32 | length 680.7
  Top Layer w10: R11.2@1373,1760.31 1373,1750.08 1378.51,1744.57 v3@1378.51,1561.49 ; v2(1560,1300) 1560.13,1299.87 1560.13,1257.63 1571.13,1246.62 1571.13,1186.48 1572.04,1185.57 1572.04,1157.05 U3.32@1572.94,1156.14
  Bottom Layer w10: v3(1390,1560) 1390,1500 1560,1330 v2(1560,1300)
AIN1: J2.2 R17.2 U3.10 | length 1982.9
  Top Layer w10: R17.2@930,639.69 v2(930,710) ; U3.10@1632,923.86 1632,873.38 1637.99,867.39 1637.99,826.64 1649.8,814.82 1660,804.61 v5(1660,765)
  Bottom Layer w10: J2.2@450,1050 501,999 501,833 578.6,755.4 584.86,755.4 584.91,755.35 930,755.35 ; v2(930,710) 930,755.35 ; v5(1660,765) 1660,745 1672.87,732.13 1672.87,592.87 1661,581 1373,581 1198.65,755.35 930,755.35
AIN2: J4.2 R18.2 U3.11 | length 1823.9
  Top Layer w10: R18.2@880,639.69 v2(880,710) ; U3.11@1651.68,923.86 1651.68,878.97 1655.87,874.79 1655.87,834.04 1667.68,822.23 ; 1667.68,822.21 1700,789.89 v5(1700,750)
  Bottom Layer w10: J4.2@450,713 527,636 685.29,636 704.65,655.35 880,655.35 ; v2(880,710) 880,655.35 ; v5(1700,750) 1700,580 1683.13,563.13 1354.87,563.13 1262.65,655.35 880,655.35
AISENN: C18.2 NT6.1 U3.33 | length 815.6
  Top Layer w10: C18.2@1529.69,1330 1529.87,1329.81 v2@1529.87,1270.13 ; v2(1530,1270) 1530,1262.47 1553.26,1239.21 U3.33@1553.26,1156.14
  Bottom Layer w10: v3@1095,1460 1128.13,1426.87 1128.13,1353.63 1150,1331.75 1150,1330 1300,1180 1440,1180 v2(1530,1270)
  other v3: 1095,1451.09
AISENP: C18.1 NT8.1 U3.34 | length 878.2
  Top Layer w10: NT8.1@1095,1685 1095,1665 1106.38,1653.62 1336.38,1653.62 1360,1630 v3(1360,1530) ; C18.1@1490.32,1330 1480,1319.68 v2(1480,1300) 1480,1277.75 1531.76,1225.99 1531.76,1186.48 1532.67,1185.57 U3.34@1532.67,1157.05
  Bottom Layer w10: v3(1360,1530) 1360,1500 1480,1380 v2(1480,1300)
AOUT1: NT1.1 U3.37 | length 1072.8
  Top Layer w10: NT1.1@900,1735 900.28,1734.72 900.28,1664.45 946.85,1617.87 1247.4,1617.87 1275.28,1590 v3(1300,1590) ; v2(1340,1230) 1433.54,1230 1474.52,1189.02 U3.37@1474.52,1156.14
  Bottom Layer w10: v3(1300,1590) 1300,1572.25 1270.13,1542.37 1270.13,1299.87 v2@1330,1240
AOUT2: NT2.2 U3.30 | length 594.5
  Top Layer w10: NT2.2@1396.39,1665 1396.39,1595.86 1450,1542.25 v3@1450,1540 ; U3.30@1612.31,1156.14 1612.31,1250.07 1619.87,1257.63 v2@1619.87,1299.87
  Bottom Layer w10: v3(1450,1530) 1450,1500 1620,1330 v2(1620,1300)
B1HS: R12.1 U3.27 | length 717.7
  Top Layer w10: U3.27@1671.37,1156.14 1671.37,1249.12 1679.87,1257.63 v2@1679.87,1299.87 ; v3(1860,1590) 1870,1600 R12.1@1870,1790.32
  Bottom Layer w10: v2(1680,1300) 1680,1354.53 1827.74,1502.26 1827.74,1560.13 1857.61,1590 v3(1860,1590)
B1LS: R14.1 U3.26 | length 679
  Top Layer w10: U3.26@1691.06,1156.14 1691.06,1227.44 1710,1246.39 v2@1710,1260 ; v3@1920,1560 1920,1746.69 1930,1756.69 R14.1@1930,1760.32
  Bottom Layer w10: v2(1710,1270) 1710,1350 v3(1910,1550)
B2HS: R13.2 U3.22 | length 964.3
  Top Layer w10: U3.22@1770.7,1156.14 U3.22@1769.8,1156.14 1769.8,1199.8 1840,1270 v2(1870,1270) ; v2(2399.69,1600) R13.2@2430,1630.31
  Bottom Layer w10: v2(1870,1270) 1862.25,1277.75 1862.25,1390 2052.25,1580 2379.69,1580 v2(2399.69,1600)
B2LS: R15.2 U3.23 | length 592.3
  Top Layer w10: U3.23@1751.02,1156.14 U3.23@1750.11,1156.14 1750.11,1207.31 1820,1277.2 v2(1820,1300) ; R15.2@1990.31,1630 2000,1620.31 v3(2000,1570)
  Bottom Layer w10: v2(1820,1300) 1820,1390 v3(2000,1570) v3@2000,1560
BIN1: J6.2 R20.2 U3.12 | length 1980.9
  Top Layer w10: U3.12@1672.28,922.95 U3.12@1671.37,923.86 1671.37,884.56 1673.74,882.19 1673.74,841.44 1685.55,829.63 ; 1685.55,829.62 1750.92,764.25 ; 1750.93,764.25 1775.18,740 v2@1840,740 ; v2(1855,580) 2028,580 2030,582 v2(2037,582) ; R20.2@2422.28,587.86 2498.14,587.86 2529,557 v2@2625,557 ; v2(2626,556) v2@2626,846
  Bottom Layer w10: v2(1850,740) 1855,735 v2(1855,580) ; v2(2037,582) 2063,556 v2(2626,556) ; v2(2630,850) J6.2@2798.16,1018.16
BIN2: J8.2 R19.2 U3.13 | length 1566.3
  Top Layer w10: U3.13@1691.06,923.86 1691.61,923.3 1691.61,848.85 1703.43,837.04 ; 1703.43,837.02 1758.32,782.13 ; 1758.33,782.13 1771.46,769 v5(1810,769) ; v2@1811,611 v2(1811.87,611.87) 2049.37,611.87 2050.25,611 v2(2070,611) ; R19.2@2370,587.5 v2(2370,630)
  Bottom Layer w10: v5(1810,769) 1811.87,767.13 v2(1811.87,611.87) ; v2(2070,611) 2107.13,573.87 2370,573.87 ; v2(2370,630) 2370,573.87 ; J8.2@2800.05,661.98 2750.05,711.98 2670,711.98 2613.37,655.35 2531.21,655.35 2449.73,573.87 2370,573.87
BISENN: C19.2 NT5.1 U3.24 | length 894.3
  Top Layer w10: U3.24@1730.43,1156.14 1730.43,1212.9 1757.75,1240.22 1757.75,1257.75 v2(1770,1270) ; C19.2@1769.69,1330 1769.75,1329.94 v2@1769.75,1270.25 ; v3@2204.66,1450.53 NT5.1@2204.66,1485
  Bottom Layer w10: v2(1770,1270) 1827.75,1270 1897.63,1200.13 1922.37,1200.13 1939.87,1217.63 1939.87,1242.37 1930,1252.25 1930,1370 2020,1460 v3@2200,1460
  other v3: 2204.66,1447.93
BISENP: C19.1 NT7.1 U3.25 | length 920
  Top Layer w10: U3.25@1710.74,1156.14 1711.65,1156.14 1711.65,1219.4 1739.87,1247.63 v2(1739.87,1300) 1739.87,1306.66 1730.32,1316.22 C19.1@1730.32,1330 ; v3@1940,1570 v3(1950,1570) 1950,1640 1967.68,1657.68 2197.68,1657.68 2205,1665 NT7.1@2205,1685
  Bottom Layer w10: v2(1739.87,1300) 1739.87,1349.87 1900,1510 1912.25,1510 1950,1547.75 v3(1950,1570)
BOUT1: NT3.1 U3.28 | length 686.4
  Top Layer w10: U3.28@1651.68,1156.14 v2@1651.68,1268.32 ; v3(1815.36,1590) 1845.24,1560.13 1872.37,1560.13 1900,1587.75 NT3.1@1900,1665
  Bottom Layer w10: v2(1650,1270) 1650,1360 1790,1500 1790,1564.64 v3(1815.36,1590)
BOUT2: NT4.2 U3.21 | length 1059.2
  Top Layer w10: U3.21@1789.48,1156.14 1789.48,1189.48 1830,1230 v2(1910,1230) ; v3@2030,1510 2030,1583 2064.87,1617.87 2363.15,1617.87 2400,1654.72 NT4.2@2400,1755
  Bottom Layer w10: v2(1910,1230) 1910,1390 v3(2020,1500)
GND: C1.1 C2.1 C3.1 C4.1 C5.1 C6.1 C7.2 C10.1 C11.2 C12.2 C13.2 C14.2 C15.2 C16.2 C17.2 D5.2 D7.1 J2.1 J4.1 J6.1 J8.1 J9.1 J13.1 J14.1 J14.2 NT5.2 NT6.2 R1Sense.1 R2Sense.1 R3Sense.1 R4Sense.1 R7.1 U1.1 U2.1 U3.5 U3.19 U3.29 U3.38 U3.39 | length 587.3
  Top Layer w10: C3.1@1333,337.56 1391,337.56 C1.1@1391,387.44 ; 1454.83,1080.83 U3.38@1454.83,1156.14 ; C7.2@1518.5,755 1517.13,756.38 1517.13,867.13 1533.57,883.57 U3.5@1533.57,923.86 1533.57,1003.57 ; U3.39@1632,1068 U3.29@1632,1156.14 ; C6.1@2320,337.56 C5.1@2380,337.56
  other v1: 208,66 308,66 408,66 508,66 608,66 708,66 808,66 908,66 1308,66 1408,66 1508,66 1608,66 1708,66 1808,66 1908,66 2008,66 2308,66 2408,66 2508,66 2608,66 2708,66 2808,66 2908,66 3008,66 3108,66 158,166 258,166 1358,166 1458,166 1658,166 1758,166 1858,166 1958,166 3058,166 3158,166 3258,166 108,266 208,266 3108,266 3208,266 158,366 358,366 1458,366 1758,366 2758,366 2958,366 3158,366 3258,366 108,466 208,466 308,466 408,466 908,466 1008,466 1108,466 1208,466 2808,466 3008,466 3108,466 3208,466 158,566 258,566 958,566 1058,566 1158,566 1258,566 2958,566 3058,566 3158,566 3258,566 108,666 208,666 308,666 608,666 3008,666 3108,666 3208,666 158,766 258,766 458,766 2058,766 2158,766 2258,766 2358,766 2458,766 3258,766 108,866 208,866 308,866 408,866 608,866 708,866 808,866 908,866 1008,866 1108,866 1208,866 1308,866 2108,866 2208,866 2308,866 2408,866 2508,866 2908,866 3008,866 3108,866 3208,866 158,966 258,966 558,966 658,966 858,966 958,966 1058,966 1158,966 1258,966 1858,966 2058,966 2158,966 2258,966 2458,966 2958,966 3058,966 3258,966 108,1066 208,1066 608,1066 708,1066 808,1066 908,1066 1008,1066 1108,1066 1208,1066 1308,1066 1508,1066 1808,1066 1908,1066 2008,1066 2108,1066 2208,1066 2308,1066 2408,1066 2508,1066 2608,1066 2708,1066 2808,1066 2908,1066 3008,1066 158,1166 258,1166 358,1166 458,1166 558,1166 658,1166 758,1166 858,1166 958,1166 1058,1166 1158,1166 1258,1166 1858,1166 1958,1166 2058,1166 2158,1166 2258,1166 2358,1166 2458,1166 2558,1166 2658,1166 2758,1166 2858,1166 2958,1166 108,1266 208,1266 308,1266 408,1266 508,1266 608,1266 708,1266 808,1266 908,1266 1008,1266 1108,1266 2008,1266 2108,1266 2208,1266 2308,1266 2408,1266 2508,1266 2608,1266 2708,1266 2808,1266 2908,1266 3008,1266 158,1366 258,1366 358,1366 458,1366 558,1366 658,1366 758,1366 858,1366 958,1366 1058,1366 1158,1366 2058,1366 2158,1366 2258,1366 2358,1366 2458,1366 2558,1366 2658,1366 2758,1366 2858,1366 2958,1366 108,1466 208,1466 308,1466 408,1466 508,1466 608,1466 708,1466 808,1466 908,1466 2408,1466 2508,1466 2608,1466 2708,1466 2808,1466 2908,1466 3008,1466 358,1566 958,1566 1058,1566 1158,1566 2458,1566 2658,1566 2758,1566 2858,1566 2958,1566 108,1666 208,1666 308,1666 158,1766 258,1766 358,1766 108,1866 208,1866 308,1866 158,1966 258,1966 358,1966 308,2066 358,2166 108,2266 208,2266 308,2266 158,2366 258,2366 358,2366 2658,2366 2758,2366 2858,2366 2958,2366 3058,2366 3158,2366 3258,2366
  other v4: 1567.04,996.69 1610.35,996.69 1653.65,996.69 1696.96,996.69 1567.04,1040 1610.35,1040 1653.65,1040 1696.96,1040 1567.04,1083.31 1610.35,1083.31 1653.65,1083.31 1696.96,1083.31
MA1: J10.2 NT1.2 Q1.1 Q1.2 Q1.3 Q3.5 Q3.6 Q3.7 Q3.8 TP1.1 | length 173.3
  Top Layer w10: NT1.2@900,1765 900,1930.75 ; 900.28,1931.03 905.62,1936.37
MA2: J10.1 NT2.1 Q2.1 Q2.2 Q2.3 Q4.5 Q4.6 Q4.7 Q4.8 TP2.1 | length 278.4
  Top Layer w10: 1340,1950 1396.39,1893.61 NT2.1@1396.39,1695
MB1: J11.2 NT3.2 Q5.1 Q5.2 Q5.3 Q7.5 Q7.6 Q7.7 Q7.8 TP3.1 | length 246.5
  Top Layer w10: 1690,2158.49 1690,2160 ; NT3.2@1900,1695 1900,1940
MB2: J11.1 NT4.1 Q6.1 Q6.2 Q6.3 Q8.5 Q8.6 Q8.7 Q8.8 TP4.1 | length 155
  Top Layer w10: NT4.1@2400,1785 2400,1940
NetC2_2: C2.2 D1.1 D2.2 U1.2 U1.6 | length 967
  Top Layer w10: v2(970,386) 970,385 U1.2@1036.65,385 ; v2(971,224.21) 1080,224.21 ; D1.1@1080,175.59 1080,224.21 ; D2.2@1203.32,199.21 1203.32,224.21 ; U1.6@1243.35,335 v2@1289,335 ; v2(1269,225) 1269,224.21 1203.32,224.21 ; C2.2@1391,281.95 1391,282.44 v2@1434,282.44 ; 1080,224.21 1203.32,224.21
  Bottom Layer w10: v2(970,386) 970,224.21 v2(971,224.21) ; v2(1269,225) 1269,283 1290,283 ; v2@1290,335 1290,283 ; v2@1434,283 1290,283
  other v2: 1443,283 1293,335
NetC3_2: C3.2 U1.5 | length 86.7
  Top Layer w10: U1.5@1243.35,282.44 C3.2@1330,282.44
NetC5_2: C5.2 D3.1 D4.2 U2.2 U2.6 | length 930.8
  Top Layer w10: v2(1965,386) U2.2@2037.65,386 ; D4.2@2095,199.21 2178,199.21 ; v2(2178,385) 2178,335 ; D3.1@2220,199.21 2178,199.21 ; v2@2281,335 v2(2278,335) U2.6@2244.35,335 2178,335 ; C5.2@2380,282 v2(2423,282) ; 2178,199.21 2178,335
  Bottom Layer w10: v2(1965,386) 1965,385 v2(2178,385) ; v2@2281,335 v2(2278,335) 2278,305.27 2301.27,282 v2(2423,282)
NetC6_2: C6.2 U2.5 | length 73.1
  Top Layer w10: U2.5@2244.35,285 C6.2@2317.44,285
NetC7_1: C7.1 U3.7 | length 156.5
  Top Layer w10: U3.7@1572.94,923.86 1572.94,856.6 1584.37,845.18 1584.37,775 1581.5,775
NetC8_1: C8.1 U3.2 | length 169.7
  Top Layer w10: C8.1@1366,1030 1373.97,1030 1439.68,964.29 1462.61,964.29 1473.61,953.29 U3.2@1473.61,922.95
NetC8_2: C8.2 U3.1 | length 99.7
  Top Layer w10: C8.2@1366,950 1428.69,950 U3.1@1454.83,923.86
NetC9_1: C9.1 U3.3 | length 128.1
  Top Layer w10: C9.1@1423.32,857 1423.32,878.32 1428.43,883.43 1482.8,883.43 1493.3,893.93 1493.3,922.95 U3.3@1494.2,923.86
NetD1_2: D1.2 pad.0@300,370 R1.1 | length 1034.6
  Top Layer w10: v2(1016,100.79) D1.2@1080,100.79
  Bottom Layer w10: pad.0@300,370 R1.1@300,270 300,180 363,117 692.86,117 731.21,155.35 768.79,155.35 823.35,100.79 v2(1016,100.79)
